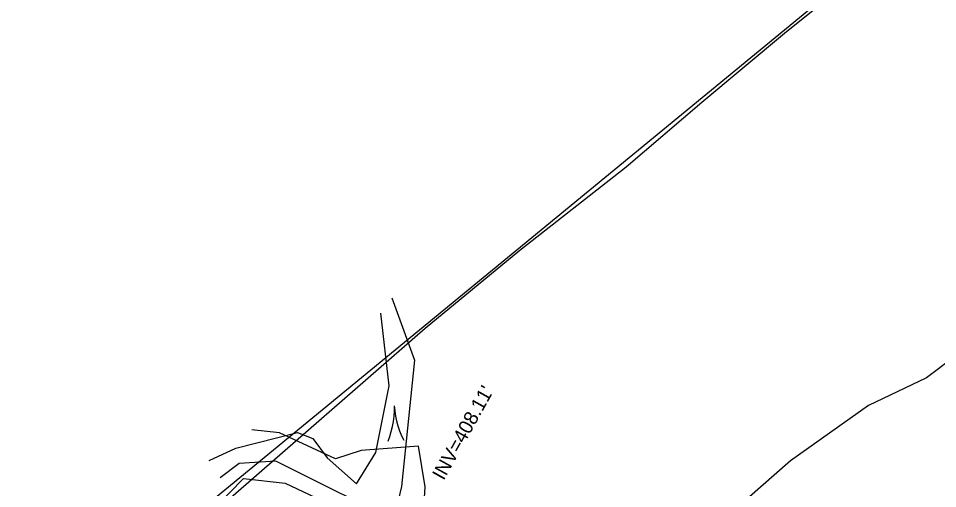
# Model space of a CAD drawing. Extents: x 2074109 to 2077820, y 741079 to 746031.
# Drawn here: x 2075438.5 to 2075699.8, y 744229 to 744362.7 of the extents above; entities that cross this region are included whole.
import ezdxf

# ---------------------------------------------------------------- set-up
doc = ezdxf.new("R2010")
doc.units = 0
for name, color, linetype in [('Exist Horizontal Alignment', 7, 'Continuous'), ('Exist Hydro Stream Flow Arrow CELL', 7, 'Continuous'), ('Exist Hydro Stream or Body of Water', 7, 'Continuous'), ('Exist Other Culture Fence Line', 7, 'Continuous'), ('Exist Right of Way Line', 7, 'Continuous'), ('Exist Structure Minor Pipes RCP 48 Inch Invert', 7, 'Continuous'), ('Exist Vegetation Woods Line', 7, 'Continuous')]:
    doc.layers.add(name, color=color, linetype=linetype)

msp = doc.modelspace()

# ---------------------------------------------------------------- linework, layer by layer
at = {"layer": 'Exist Horizontal Alignment'}
for centre, radius, start, end in [((2065746.77, 748969.72), 11283.45, 330.581241, 339.398504), ((2074798.58, 745361.18), 1469.76, 306.18995, 339.08912)]:
    msp.add_arc(centre, radius, start, end, dxfattribs=at)
at = {"layer": 'Exist Hydro Stream Flow Arrow CELL'}
msp.add_line((2075545.67, 744247.58), (2075545.67, 744247.58), dxfattribs=at)
for points in [[(2075543.6, 744242.49), (2075544.14, 744243.85), (2075544.54, 744245.29), (2075544.92, 744246.72), (2075545.17, 744248.14), (2075545.35, 744249.61), (2075545.45, 744251.11), (2075545.46, 744252.57)], [(2075548.17, 744242.68), (2075547.51, 744243.99), (2075546.99, 744245.39), (2075546.49, 744246.78), (2075546.12, 744248.18), (2075545.82, 744249.63), (2075545.6, 744251.11), (2075545.46, 744252.57)]]:
    msp.add_lwpolyline(points, dxfattribs=at)
at = {"layer": 'Exist Hydro Stream or Body of Water'}
for points in [[(2075544.73, 744283.29), (2075551.12, 744265.56), (2075547.41, 744229.65), (2075544.66, 744218.04), (2075542.23, 744216.03), (2075539.46, 744217.96), (2075536.16, 744224.81), (2075529.92, 744227.74), (2075511.75, 744236.8), (2075501.32, 744236.15), (2075495.85, 744232.06)], [(2075492.77, 744237.07), (2075500.37, 744240.5), (2075517.92, 744244.95), (2075522.19, 744243.27), (2075526.32, 744237.75), (2075534.63, 744230.44), (2075540.16, 744239.32), (2075543.94, 744258.26), (2075541.58, 744278.86)]]:
    msp.add_lwpolyline(points, dxfattribs=at)
at = {"layer": 'Exist Other Culture Fence Line'}
msp.add_lwpolyline([(2075690.21, 744385.61), (2075656.34, 744358.38), (2075632.77, 744338.73), (2075611.28, 744320.39), (2075581.11, 744296.73), (2075554.17, 744274.55), (2075497.37, 744225.11), (2075457.53, 744193.95), (2075418.99, 744163.3)], dxfattribs=at)
at = {"layer": 'Exist Right of Way Line'}
msp.add_line((2075289.65, 744058.22), (2075694.31, 744390.69), dxfattribs=at)
at = {"layer": 'Exist Vegetation Woods Line'}
for points in [[(2076035.25, 744661.7), (2076004.84, 744606.77), (2075976.36, 744564.25), (2075951.89, 744530.59), (2075930.35, 744505.47), (2075909.71, 744473.91), (2075872.32, 744424.89), (2075842.27, 744395.14), (2075808.52, 744358.81), (2075764.72, 744313.77), (2075734.25, 744288.86), (2075696.68, 744260.54), (2075680.23, 744252.64)], [(2075680.23, 744252.64), (2075658.01, 744236.93), (2075637.81, 744219.2), (2075616.25, 744204.45), (2075603.67, 744195.04), (2075591.15, 744173.96), (2075576.21, 744153.79), (2075556.35, 744153.49)], [(2075469.64, 744196.76), (2075478.89, 744206.76), (2075490.72, 744219.81), (2075502.55, 744231.89), (2075514.37, 744230.62), (2075529.82, 744223.32), (2075537.82, 744215.3), (2075547.55, 744209.65), (2075553.23, 744213.86), (2075554.19, 744229.57), (2075552.23, 744241.14), (2075535.96, 744239.9), (2075528.63, 744237.52), (2075512.79, 744244.88), (2075504.86, 744245.71)]]:
    msp.add_lwpolyline(points, dxfattribs=at)

# ---------------------------------------------------------------- texts
at = {"layer": 'Exist Structure Minor Pipes RCP 48 Inch Invert'}
msp.add_text("INV=408.11'", height=4, rotation=60.742, dxfattribs=at).set_placement((2075559.41, 744231.16))

doc.saveas('drawing.dxf')
